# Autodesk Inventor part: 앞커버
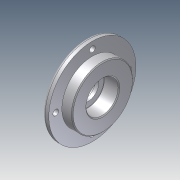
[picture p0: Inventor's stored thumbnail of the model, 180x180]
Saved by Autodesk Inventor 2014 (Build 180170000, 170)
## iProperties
Company: 한국ATC센터
Created: 2014-01
Part Number: 앞커버
Document SubType Name: Modeling
Designer: KYOUNG IL JANG
Density: 1 g/cm^3
Material: 일반
Mass: 88.8969 g
Surface Area: 235.103 cm^2
Volume: 88.8969 cm^3
Vendor: CBT Solutions
Appearance: 기본값
Author: KYOUNG IL JANG
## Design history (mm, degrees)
sketch "스케치1"
  geometry: L1 (-15, -35)-(-15, 35) reference; L2 (-15, 35)-(67, 35) reference; L3 (-3, 25)-(-3, -10.613) reference; L4 (0, 0)-(-32, 0); L5 (-3, 0)-(-3, 35); L6 (-3, 35)-(-15, 35); L7 (-15, 35)-(-15, 50); L8 (-15, 50)-(-22, 50); L9 (-22, 50)-(-22, 22.5); L10 (-22, 22.5)-(-32, 22.5); L11 (-32, 22.5)-(-32, 0); L12 (-3, 18.5)-(-20, 18.5); L13 (-20, 18.5)-(-20, 12.5); L14 (-20, 12.5)-(-24, 12.5); L15 (-24, 12.5)-(-24, 16); L16 (-24, 16)-(-32, 16)
  constraints: 28 end point, 7 perpendicular, 6 parallel, 5 point on line, 1 horizontal, 1 other
  dimensions: "d0" = 7 distance of L7.end L8.end; "d1" = 45 diameter of L10 L4; "d2" = 10 distance of L9.end L10.end; "d3" = 37 diameter of L12 L4; "d4" = 17 distance of L12.start L12.end; "d5" = 32 diameter of L16 L4; "d6" = 8 distance of L15.end L16.end; "d7" = 25 diameter of L14 L4; "d8" = 100 diameter of L8 L4
revolve "회전1" sketch "스케치1" stored, may be unused: angle "d9" = 90 deg
fillet "모깎기1" dims "d10" = 3, "d11" = 0.3
chamfer "모따기1" distance "d12" = 1; stored, may be unused: second distance "d13" = 2, angle "d14" = 45 deg
sketch "스케치2"
  geometry: 2 further points
  constraints: 1 vertical alignment
  dimensions: "d15" = 42 distance of point (0, 0) point (0, 42)
hole "구멍1" sketch "스케치2" at (0, 42) diameter "d16" = 6.6; stored, may be unused: countersink angle "d20" = 90 deg, drill point angle "d22" = 118 deg; dims "d17" = 6, "d18" = 4, "d19" = 2, "d21" = 8
node "솔리드1"
pattern_circular "원형 패턴1" dims angle "d24" = 360 deg
node "참조1"
node "참조2"
